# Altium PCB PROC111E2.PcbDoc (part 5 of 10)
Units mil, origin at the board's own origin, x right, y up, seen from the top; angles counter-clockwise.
Board outline 7700 x 2300 mil, 6 copper layers (Top Layer, GND 1, SIG 1, SIG 2, GND 2, Bottom Layer), stack 78.711 mil thick; 767 components, 596 nets, 2755 pads, 1578 vias.
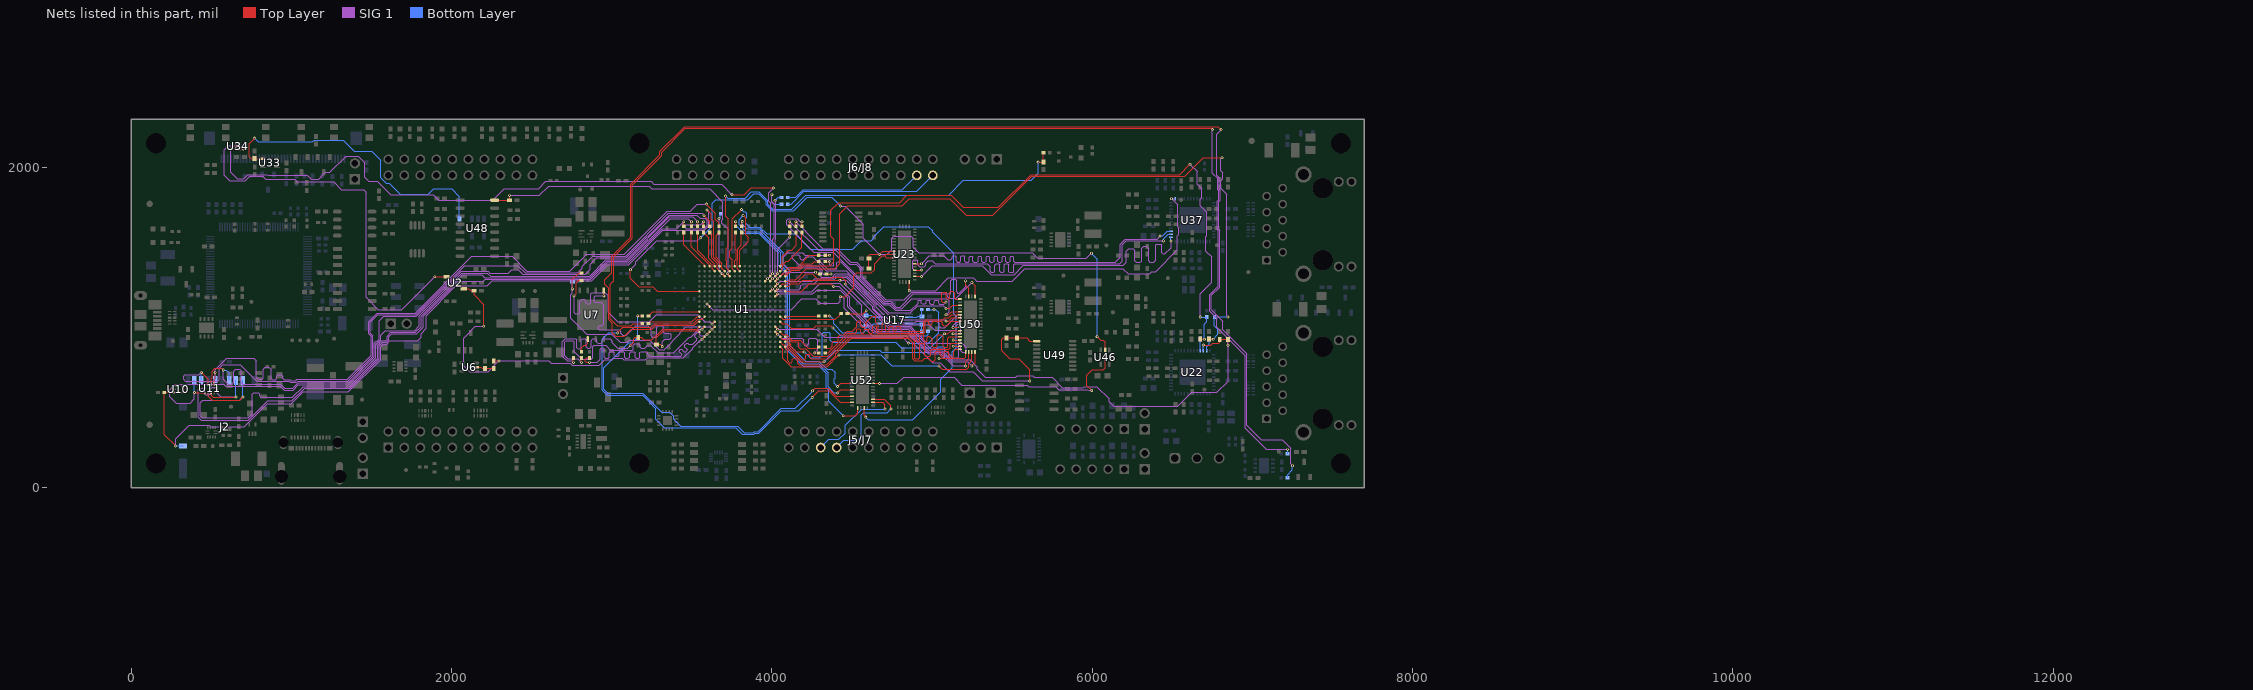
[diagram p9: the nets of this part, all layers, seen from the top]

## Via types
v1: diameter 18, hole 8, Top Layer to Bottom Layer, tented both sides, 1474 vias
v2: diameter 19.68, hole 7.87, Top Layer to Bottom Layer, tented both sides, 104 vias

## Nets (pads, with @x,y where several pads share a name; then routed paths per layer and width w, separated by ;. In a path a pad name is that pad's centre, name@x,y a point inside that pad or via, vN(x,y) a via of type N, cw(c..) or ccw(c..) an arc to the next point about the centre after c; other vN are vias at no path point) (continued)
AM263_ICSSM_MII0_TXD1: U23.27 U37.27 | length 2238.5
  Top Layer w5.3: U23.27@4892.17,1397.44 v1(4933.82,1397.44)
  SIG 1 w4.75: v1(4933.82,1397.44) 4982.58,1446.2 5073.64,1446.2 5097.17,1422.67 5116.6,1422.67 5125,1431.08 5125,1441.2 5130,1446.2 5145.03,1446.2 5150,1441.23 5150,1415.63 5157.93,1407.7 5171.95,1407.7 5180,1415.76 5180,1441.63 5184.57,1446.2 5200,1446.2 5204.29,1441.91 5204.29,1413.41 5210,1407.7 5225,1407.7 5231.71,1414.41 5231.71,1439.62 5237.09,1445 5250,1445 5255,1440 5255,1412.7 5260,1407.7 5280,1407.7 5286.71,1414.41 5286.71,1439.62 5292.09,1445 5305,1445 5310,1440 5310,1412.7 5315,1407.7 5330,1407.7 5336.71,1414.41 5336.71,1439.62 5342.09,1445 5355,1445 5360,1440 5360,1412.7 5365,1407.7 5380,1407.7 5386.71,1414.41 5386.71,1439.62 5392.09,1445 5405,1445 5410,1440 5410,1412.7 5415,1407.7 5430,1407.7 5436.71,1414.41 5436.71,1439.62 5442.09,1445 5455,1445 5460,1440 5460,1412.7 5465,1407.7 5480,1407.7 5486.71,1414.41 5486.71,1439.62 5492.09,1445 5505,1445 5510,1440 5510,1412.7 5515.18,1407.52 6145,1407.52 6175,1437.52 6175,1520.85 6206.45,1552.3 6404.57,1552.3 v1(6423.51,1571.24)
  Bottom Layer w5.3: v1(6423.51,1571.24) 6439.75,1571.24 6469.65,1601.14 U37.27@6491.32,1601.14
AM263_ICSSM_MII0_TXD2: U23.25 U37.26 | length 2245.1
  Top Layer w5.3: U23.25@4892.17,1358.07 v1(4933.82,1358.07)
  SIG 1 w4.75: v1(4933.82,1358.07) 4885,1358.07 4877.81,1365.27 4877.81,1413.87 4886.61,1422.67 4903.59,1422.67 4910,1416.26 4910,1391.44 4923.24,1378.19 4952.19,1378.19 4961,1387 4961,1401.85 4975.85,1416.69 4999.73,1416.69 5018.95,1397.47 5343.6,1397.47 5361.5,1379.57 5361.5,1351.08 5369.16,1343.42 5385.21,1343.42 5391.78,1349.99 5391.78,1389.25 5400,1397.47 5415,1397.47 5422.49,1389.98 5422.49,1350.49 5428.06,1344.92 5445.48,1344.92 5450,1349.43 5450,1390 5457.47,1397.47 5472.53,1397.47 5480,1390 5480,1348.38 5484.96,1343.42 5506.27,1343.42 5510,1347.15 5510,1392.47 5515,1397.47 6171.47,1397.47 6187.84,1413.84 6187.84,1517.25 6211.44,1540.85 v1(6444.47,1540.85)
  Bottom Layer w5.3: v1(6444.47,1540.85) 6444.47,1550.71 6475.21,1581.46 U37.26@6491.32,1581.46
AM263_ICSSM_MII0_TXD3: U23.23 U37.25 | length 2244.1
  Top Layer w5.3: U23.23@4892.17,1318.7 v1(4933.82,1318.7)
  SIG 1 w4.75: v1(4933.82,1318.7) 4999.46,1384.35 5314.02,1384.35 5369,1329.37 5512.23,1329.37 5570.29,1387.42 6195,1387.42 6213.36,1405.78 6213.36,1475.71 6227.65,1490 6254.55,1490 6265,1479.55 6265,1415.76 6275.11,1405.64 6300.52,1405.64 6307.97,1413.09 6307.97,1493.37 6320.6,1506 6336.86,1506 6351.36,1491.5 6351.36,1415.04 6360.4,1406 6383.17,1406 6397.17,1420 6397.17,1517.17 6401,1521 6430.92,1521 6434.76,1517.16 6434.76,1466.56 6442.03,1459.28 6452.69,1459.28 6492.17,1498.76 v1(6492.17,1540)
  Bottom Layer w5.3: U37.25@6491.32,1561.77 6491.32,1540.85 v1(6492.17,1540)
AM263_ICSSM_MII0_TXEN: U23.21 U37.37 | length 2239.7
  Top Layer w5.3: U23.21@4856.73,1283.27 4856.73,1230.38 v1(4857.11,1230)
  SIG 1 w4.75: v1(4857.11,1230) 5021.49,1230 5101.48,1309.99 5257.38,1309.99 5277.42,1289.95 5501.24,1289.95 5578.61,1367.32 6190.85,1367.32 6223.21,1334.96 6360.2,1334.96 6373.06,1347.82 6395.09,1347.82 6531.62,1484.35 6531.62,1572.37 6539.25,1580 6539.25,1622.97 6534.22,1628 6534.22,1764.68 v1(6495,1803.9)
  Bottom Layer w5.3: v1(6495,1803.9) U37.37@6516.91,1803.9
AM263_ICSSM_MII1_COL: R112.1 R124.2 R225.2 U1.C18 U22.45 | length 4456.8
  Top Layer w5.3: U1.C18@4082.57,1319.8 4086.6,1319.8 4122.5,1355.7 4170.68,1355.7 4201.68,1386.7 4363.56,1386.7 4387.19,1410.33 4387.19,1550.12 4367.66,1569.64 4367.66,1731.16 4416.75,1780.25 4796.75,1780.25 4840.66,1824.16 5119.95,1824.16 5194.97,1749.14 5412.42,1749.14 5618.28,1955 6545.79,1955 v1(6610,2019.21) ; R112.1@6674.39,926.46 v1(6700,926.46)
  SIG 1 w4.75: v1(6610,2019.21) 6655.14,1974.08 6655.14,1894.1 6684.3,1864.93 6684.3,1809.3 6674.82,1799.82 6674.82,1760.85 6716.13,1719.54 6716.13,1573.87 6710,1567.73 6710,1475.5 6745.5,1440 6745.5,1282.11 6674.39,1211 v1(6674.39,1065)
  Bottom Layer w5.3: U22.45@6674.39,853.9 6674.52,854.03 6674.52,926.32 R124.2@6674.39,926.46 v1(6700,926.46) 6700,1020 6715,1035 R225.2@6715,1064.94 6674.45,1064.94 v1(6674.39,1065)
AM263_ICSSM_MII1_RXCLK: U1.E16 U50.31 | length 1530.3
  Top Layer w5.3: v1(5131.16,1000.35) U50.31@5173.43,1000.35
  Top Layer w10: U1.E16@4019.57,1256.81 v1(4035.32,1272.56)
  SIG 1 w4: v1(4035.32,1272.56) 4051.82,1289.06 4114.06,1289.06
  SIG 1 w4.75: 4114.06,1289.06 4250.66,1289.06 4265.61,1304 4379.88,1304 4400.29,1324.4 4466.88,1324.4 4650,1141.28 4650,1127.38 4749.39,1027.99 4891.44,1027.99 4901.66,1038.21 5029.44,1038.21 5045,1022.66 5045,1007.89 5055.05,997.84 5080.12,997.84 5163.56,1081.29 5170.68,1081.29 5177.73,1074.24 5177.73,1041.58 5168.72,1032.57 5150.46,1032.57 5131.16,1013.27 v1(5131.16,1000.35)
AM263_ICSSM_MII1_RXD0: U1.F18 U50.42 | length 1527.9
  Top Layer w4: U1.F18@4082.57,1225.32 4113.77,1225.32 4114.06,1225.03
  Top Layer w5.3: 4114.06,1225.03 4115.16,1223.93 4182.78,1223.93 4232.43,1273.58 4368.23,1273.58 v1(4384.99,1256.82) ; v1(5248.23,759.55) 5267.91,779.23 U50.42@5267.91,846.81
  SIG 1 w4.75: v1(4384.99,1256.82) 4417.5,1256.82 4484.56,1189.75 4484.56,1133.75 4640.56,977.74 4847.67,977.74 4979.44,845.97 5058.54,845.97 5119.51,785 5222.77,785 v1(5248.23,759.55)
AM263_ICSSM_MII1_RXD1: U1.G16 U50.40 | length 1530
  Top Layer w5.3: v1(5208.86,759.55) 5208.86,785.31 5228.54,805 U50.40@5228.54,846.81
  Top Layer w10: U1.G16@4019.57,1193.82 v1(4035.32,1209.57)
  SIG 1 w4.75: v1(4035.32,1209.57) 4254.57,1209.57 4278.13,1233.13 4426.97,1233.13 4474.51,1185.59 4474.51,1129.58 4636.4,967.69 4843.5,967.69 4975.28,835.92 5054.38,835.92 5130.76,759.55 v1(5208.86,759.55)
AM263_ICSSM_MII1_RXD2: U1.E17 U50.37 | length 1526
  Top Layer w4: U1.E17@4051.07,1256.81 4066.82,1272.56 4101.95,1272.56 4113.62,1284.23 4114.06,1284.23
  Top Layer w5.3: 4114.06,1284.23 4158.05,1284.23 4210.42,1336.6 4250.64,1336.6 4281.86,1305.38 4367.8,1305.38 4377.05,1314.63 4436.95,1314.63 4460,1291.58 v1(4460,1271.09) ; v1(5131.77,882.24) U50.37@5173.43,882.24
  SIG 1 w4.75: v1(4460,1271.09) 4460,1264.54 4726.7,997.84 4860.42,997.84 4990.73,867.53 5070.26,867.53 5127.8,810 5158.56,810 5166.28,817.72 5166.28,868.95 5152.99,882.24 v1(5131.77,882.24)
AM263_ICSSM_MII1_RXD3: U1.E18 U50.35 | length 1529
  Top Layer w4: U1.E18@4082.57,1256.81 4104.96,1256.81
  Top Layer w5.3: 4104.96,1256.81 4121.72,1273.58 4171.45,1273.58 4192.65,1294.78 4372.19,1294.78 4372.51,1295.1 v1(4423.69,1295.1) ; v1(5131.77,921.61) U50.35@5173.43,921.61
  SIG 1 w4.75: v1(4423.69,1295.1) 4463.21,1295.1 4627.76,1130.55 4627.76,1113.02 4732.9,1007.89 4864.58,1007.89 4970.98,901.49 5157.7,901.49 5180,879.19 5180,853.61 5188.61,845 5208.86,845 5213.86,850 5213.86,875 5167.25,921.61 v1(5131.77,921.61)
AM263_ICSSM_MII1_RXDV: U1.F16 U50.33 | length 1526.7
  Top Layer w5.3: v1(5131.16,960.98) U50.33@5173.43,960.98
  Top Layer w10: U1.F16@4019.57,1225.32 v1(4035.32,1241.06)
  SIG 1 w4.75: v1(4035.32,1241.06) 4041.58,1234.81 4166.03,1234.81 4180,1248.78 4180,1259.38 4193.93,1273.3 4265,1273.3 4285.64,1293.95 4384.05,1293.95 4404.45,1314.35 4462.72,1314.35 4639.95,1137.12 4639.95,1115.05 4737.06,1017.94 4979.18,1017.94 5016.02,981.1 5142.47,981.1 5150.41,989.04 5150.41,1010.7 5159.71,1020 5173.32,1020 5177.73,1015.59 5177.73,969.09 5169.62,960.98 v1(5131.16,960.98)
AM263_ICSSM_MII1_RXER: R111.1 R123.2 R229.2 U1.F15 U22.46 | length 3862.9
  Top Layer w5.3: v1(6695,890) 6740,890 6751.09,901.09 6789.71,901.09 6795,906.38 6795,924.79 R111.1@6796.28,926.06 R123.2@6848,926.06 v1(6848,888.56)
  Top Layer w10: U1.F15@3988.08,1225.32 v1(4003.83,1241.06)
  SIG 1 w4.75: v1(4003.83,1241.06) 4019.95,1224.94 4048.81,1224.94 4051.93,1221.82 4248.36,1221.82 4302.6,1276.07 4415.5,1276.07 4415.71,1275.85 4422.39,1275.85 4560.42,1137.83 4560.42,1075.24 4647.86,987.79 4851.83,987.79 4983.6,856.02 5062.71,856.02 5120.89,797.83 5237.16,797.83 5283.33,751.67 5283.33,738.42 5332.03,689.72 5522.81,689.72 5531.21,698.12 5627.08,698.12 5636.35,688.86 5748.88,688.86 5813.88,623.85 5944.6,623.85 5951.6,630.85 6027.48,630.85 6104.93,553.4 6104.93,537.03 6133.73,508.23 6533.47,508.23 6619.77,594.53 6777.57,594.53 6848,664.96 v1(6848,888.56)
  Bottom Layer w5.3: U22.46@6694.07,853.9 6694.07,889.07 v1(6695,890) ; R229.2@6846.59,927.98 6846.59,889.97 v1(6848,888.56)
AM263_ICSSM_MII1_RXLINK: R110.1 R122.2 R227.2 U1.D18 U22.47 | length 4713.3
  Top Layer w5.3: U1.D18@4082.57,1288.31 4100.01,1288.31 4109.25,1297.55 4146.88,1297.55 4214.83,1365.5 4390.53,1365.5 4423.28,1398.25 4423.28,1708.76 4473.56,1759.05 4813.05,1759.05 4856.96,1802.96 5111.16,1802.96 5212.92,1701.21 5379.48,1701.21 5622.67,1944.4 6576.79,1944.4 6692.39,2060 v1(6810,2060) ; R110.1@6729.39,926.46 v1(6755,926.46)
  SIG 1 w4.75: v1(6810,2060) 6803.55,2053.55 6803.55,1979.56 6815.53,1967.58 6815.53,1930 6802.89,1917.36 6802.89,1868.09 6839.95,1831.03 6839.95,1072.44 v1(6846.59,1065.8)
  Bottom Layer w5.3: U22.47@6713.76,853.9 6713.76,879.37 6729.39,895 R122.2@6729.39,926.46 v1(6755,926.46) 6785,956.46 6785,987.75 6762.73,1010.01 R227.2@6762.73,1065.31 6846.11,1065.31 v1(6846.59,1065.8)
AM263_ICSSM_MII1_TXCLK: R86.1 U50.18 | length 1598.7
  Top Layer w5.3: R86.1@4111,1632.17 v1(4111,1660.23) ; v1(5248.23,1280.53) 5267.91,1260.84 U50.18@5267.91,1193.26
  SIG 1 w4.75: v1(4111,1660.23) 4290.62,1480.6 4399.37,1480.6 4484.34,1395.64 4525.74,1395.64 4555,1366.38 4555,1312.77 4705.46,1162.31 4741.59,1162.31 4777.03,1126.87 4800.47,1126.87 4883.5,1209.9 5081.16,1209.9 5107.69,1183.37 5151.08,1183.37 v1(5248.23,1280.53)
AM263_ICSSM_MII1_TXCLK_R: R86.2 U1.C16 | length 310.9
  Top Layer w5.3: v1(4111,1564.73) R86.2@4111,1592.8
  Top Layer w10: U1.C16@4019.57,1319.8 v1(4035.32,1335.55)
  SIG 1 w4: v1(4035.32,1335.55) 4035.32,1414.29
  SIG 1 w4.75: 4035.32,1414.29 4035.32,1489.06 v1(4111,1564.73)
AM263_ICSSM_MII1_TXD0: R81.1 U50.28 | length 1671.4
  Top Layer w5.3: R81.1@4331.94,1450.76 v1(4360,1450.76) ; v1(5086.77,1039.72) 5087.15,1040.1 5103.84,1040.1 5123.15,1059.41 U50.28@5173.43,1059.41
  SIG 1 w4.75: v1(4360,1450.76) 4205.76,1450.76 4190.82,1465.69 4097.29,1465.69 4071.14,1439.55 4071.14,1395.68 4092.58,1374.25 4280.76,1374.25 4300.52,1354.49 4300.52,1322.3 4308.78,1314.05 4375.72,1314.05 4396.13,1334.45 4471.04,1334.45 4728.5,1077 4779.38,1077 4807.3,1049.09 5077.41,1049.09 v1(5086.77,1039.72)
AM263_ICSSM_MII1_TXD0_R: R81.2 U1.B18 | length 251.2
  Top Layer w5.3: U1.B18@4082.57,1351.3 4108.55,1377.29 4159.8,1377.29 4233.26,1450.76 R81.2@4292.57,1450.76
AM263_ICSSM_MII1_TXD1: R82.1 U50.26 | length 1617.1
  Top Layer w5.3: R82.1@4187,1632.17 v1(4187,1660.23) ; v1(5086.77,1079.09) 5104.16,1079.09 5123.85,1098.78 U50.26@5173.43,1098.78
  SIG 1 w4.75: v1(4187,1660.23) 4176.22,1660.23 4156.97,1679.48 4102.64,1679.48 4091.48,1668.32 4091.48,1641.03 4262.23,1470.28 4383.28,1470.28 4701.77,1151.79 4737.89,1151.79 4772.86,1116.82 4810,1116.82 4873.1,1179.92 5092.29,1179.92 5106.3,1165.92 5106.3,1098.62 v1(5086.77,1079.09)
AM263_ICSSM_MII1_TXD1_R: R82.2 U1.B17 | length 304.3
  Top Layer w4: U1.B17@4051.07,1351.3 4068.69,1368.92 4068.69,1392.52 4076.15,1399.98
  Top Layer w5.3: 4076.15,1399.98 4090.36,1414.19 4101.39,1414.19 4187,1499.81 R82.2@4187,1592.8
AM263_ICSSM_MII1_TXD2: R83.1 U50.24 | length 1593.5
  Top Layer w5.3: R83.1@4339.69,1333.3 v1(4367.75,1333.3) ; v1(5086.77,1118.46) 5110.31,1118.46 5130,1138.15 U50.24@5173.43,1138.15
  SIG 1 w4.75: v1(4367.75,1333.3) 4320.82,1333.3 4313.29,1340.83 4313.29,1355.93 4284.87,1384.35 4173.89,1384.35 4126.25,1431.99 4126.25,1449.82 4131.71,1455.28 4162.45,1455.28 4175,1442.73 4175,1430.4 4183.34,1422.07 4193.93,1422.07 4212.49,1440.63 4254.37,1440.63 4340.2,1354.8 4464.91,1354.8 4729.02,1090.69 4864.78,1090.69 4909.09,1135 5070.23,1135 v1(5086.77,1118.46)
AM263_ICSSM_MII1_TXD2_R: R83.2 U1.D16 | length 309
  Top Layer w5.3: v1(4272.16,1344.87) 4283.66,1333.37 4300.24,1333.37 R83.2@4300.31,1333.3
  Top Layer w10: U1.D16@4019.57,1288.31 v1(4035.32,1304.06)
  SIG 1 w4.75: v1(4035.32,1304.06) 4076.13,1344.87 v1(4272.16,1344.87)
AM263_ICSSM_MII1_TXD3: R84.1 U50.22 | length 1639.7
  Top Layer w5.3: R84.1@4331.94,1410.76 v1(4360,1410.76) ; v1(5086.77,1157.83) 5065.63,1157.83 5060,1163.46 5060,1212.97 5066.68,1219.65 5083.67,1219.65 5086.77,1216.55 5086.77,1186.62 5094.7,1178.69 5102.75,1178.69 5108.69,1184.63 5108.69,1219.52 5115,1225.83 5129.17,1225.83 5140,1215 5140,1182.52 5145,1177.52 U50.22@5173.43,1177.52
  SIG 1 w4.75: v1(4360,1410.76) 4360,1390.84 4366.49,1384.35 4382.1,1384.35 4386.47,1388.71 4386.47,1405.96 ; 4386.49,1405.98 4386.49,1426.18 4382.66,1430 4301.19,1430 4293.86,1422.67 4293.86,1415.35 4344.21,1365 4402.22,1365 4405,1367.78 4405,1405.86 4409.89,1410.76 4428.59,1410.76 4697.6,1141.74 4733.73,1141.74 4768.7,1106.77 4866.65,1106.77 4912.39,1152.51 4912.39,1165.47 4916.79,1169.87 4928.94,1169.87 4932.42,1166.39 4932.42,1152.63 4938.17,1146.88 4956.11,1146.88 4963.82,1154.59 4963.82,1166.39 4967.3,1169.87 4982.03,1169.87 4985,1166.9 4985,1150.05 4990,1145.05 5010,1145.05 5014.57,1149.62 5014.57,1163.89 5020,1169.32 5034.12,1169.32 5040,1163.44 5040,1150.05 5045,1145.05 5073.99,1145.05 v1(5086.77,1157.83)
AM263_ICSSM_MII1_TXD3_R: R84.2 U1.C17 | length 279.2
  Top Layer w5.3: U1.C17@4051.07,1319.8 4068.04,1336.78 4088.58,1336.78 4118.11,1366.3 4166.29,1366.3 4197.29,1397.3 4251.73,1397.3 4265.18,1410.76 R84.2@4292.57,1410.76
AM263_ICSSM_MII1_TXEN: R85.1 U50.20 | length 1660.3
  Top Layer w5.3: R85.1@4149,1632.17 v1(4149,1660.23) ; v1(5208.86,1290.74) 5208.86,1264.69 5228.54,1245 U50.20@5228.54,1193.26
  SIG 1 w4.75: v1(4149,1660.23) 4209.95,1599.28 4209.95,1598.74 4318.04,1490.65 4407.8,1490.65 4492.77,1405.69 4529.9,1405.69 4565.05,1370.54 4565.05,1316.93 4709.62,1172.36 4826.69,1172.36 4874.28,1219.95 5085.33,1219.95 5095.23,1210.05 5111.68,1210.05 5116.23,1214.6 5116.23,1291.23 5124.45,1299.45 5145.55,1299.45 5154.88,1290.12 5154.88,1221.62 5161.5,1215 5168.49,1215 5208.86,1255.37 v1(5208.86,1290.74)
AM263_ICSSM_MII1_TXEN_R: R85.2 U1.A17 | length 263.9
  Top Layer w5.3: U1.A17@4051.07,1382.8 4051.07,1387.13 4065.55,1401.61 4065.55,1443.56 4105.13,1483.15 4122.33,1483.15 4152.94,1513.76 4152.94,1588.85 R85.2@4149,1592.8
AM263_IEP0_EDC_SYNC_OUT0: J6/J8.72 R88.1 | length 862.6
  Bottom Layer w5.3: R88.1@4098.66,1812.24 4147.24,1812.24 4195.51,1860.51 4814.68,1860.51 J6/J8.72@4904.17,1950
AM263_IEP0_EDC_SYNC_OUT0_R: R88.2 U1.D15 | length 569.2
  Top Layer w10: U1.D15@3988.08,1288.31 v1(4003.83,1304.06)
  SIG 1 w4: v1(4003.83,1304.06) 4020.32,1320.55 4020.32,1414.29
  SIG 1 w4.75: v1(4018.83,1791.62) 4023.81,1786.64 4023.81,1555.11 4020.32,1551.62 4020.32,1414.29
  Bottom Layer w5.3: v1(4018.83,1791.62) 4039.45,1812.24 R88.2@4059.29,1812.24
AM263_IEP0_EDIO_DATA_IN_OUT31: J6/J8.71 R87.1 | length 980.4
  Bottom Layer w5.3: R87.1@4098.66,1769.24 4119.24,1769.24 4199.52,1849.52 4903.7,1849.52 J6/J8.71@5004.17,1950
AM263_IEP0_EDIO_DATA_IN_OUT31_R: R87.2 U1.C15 | length 636.2
  Top Layer w10: U1.C15@3988.08,1319.8 v1(4003.83,1335.55)
  SIG 1 w4: v1(4003.83,1335.55) 4003.83,1414.29
  SIG 1 w4.75: v1(3999.3,1828.52) 3999.58,1828.25 3999.58,1783.65 4013.76,1769.47 4013.76,1559.27 4003.83,1549.33 4003.83,1414.29
  Bottom Layer w5.3: v1(3999.3,1828.52) 3999.3,1783.54 4013.6,1769.24 R87.2@4059.29,1769.24
AM263_INT1_PB_GPIO123: U1.D14 U34.4 | length 4549.2
  Top Layer w4: v1(621.55,2115.47) U34.4@651.22,2115.47
  Top Layer w5.3: v1(3750,1830) 3827.92,1830 3869.54,1871.62 4009.75,1871.62 v1(4010,1871.38)
  Top Layer w10: U1.D14@3956.58,1288.31 v1(3972.33,1304.06)
  SIG 1 w4: v1(3972.33,1304.06) 3988.83,1320.55 3988.83,1414.29
  SIG 1 w4.75: v1(621.55,2115.47) 620.75,2114.67 620.75,1967.65 660.41,1928 699.92,1928 726.78,1954.85 848.11,1954.85 852.86,1950.1 1098.52,1950.1 1122.87,1925.75 1168.51,1925.75 1210.41,1967.65 1237.15,1967.65 1340,2070.5 1415,2070.5 1457,2028.5 1457,1939.5 1483,1913.5 1535.02,1913.5 1620,1828.52 1884.51,1828.52 1918.04,1795 2256.51,1795 2328.43,1866.92 2542.73,1866.92 2587.88,1912.07 3244.73,1912.07 3261.64,1895.15 3684.85,1895.15 v1(3750,1830) ; 3988.83,1414.29 3988.83,1547.33 3993.66,1552.16 3993.66,1775.35 3980.05,1788.96 3980.05,1841.43 v1(4010,1871.38)
AM263_LED_ENABLE_GPIO25: R278.2 U1.C7 U48.8 | length 2011.2
  Top Layer w5.3: U48.8@2267.28,1795 R278.2@2361.38,1795 v1(2361.38,1825)
  Top Layer w10: v1(3720.36,1335.55) U1.C7@3736.11,1319.8
  SIG 1 w4: v1(3720.36,1335.55) 3720.36,1336.08 3725.31,1341.03 3725.31,1429.98
  SIG 1 w4.75: v1(2361.38,1825) 2547.62,1825 2604.54,1881.92 3232.22,1881.92 3249.14,1865 3612.11,1865 3693.94,1783.18 3693.94,1674.39 3687.75,1668.2 3687.75,1652.26 3725.31,1614.7 3725.31,1429.98
AM263_LED_GPIO26: R303.1 R304.2 U1.B7 | length 2775.8
  Top Layer w4: 3718.25,1414.29 3718.49,1414.06 3718.49,1368.92 U1.B7@3736.11,1351.3
  Top Layer w5.3: v1(3710,1820) 3710,1695.65 3727.37,1678.28 3727.37,1502.62 3715.65,1490.9 3715.65,1416.89 3718.25,1414.29 ; v1(5662,2032.26) R304.2@5695.31,2032.26 R303.1@5695.31,2090.86
  Bottom Layer w5.3: v1(3710,1820) 3710.6,1820 3722.29,1808.32 3832.65,1808.32 3871.7,1847.37 3918.43,1847.37 3974.4,1791.4 3974.4,1768.74 4004.86,1738.28 4123.33,1738.28 4210.05,1825 5102.5,1825 5195.5,1918 5618.43,1918 5662,1961.58 v1(5662,2032.26)
AM263_LIN1_RXD: U1.A9 U52.33 | length 1944.5
  Top Layer w4: 3797.83,1414.29 3797.83,1384.07 U1.A9@3799.1,1382.8
  Top Layer w5.3: 3797.83,1414.29 3797.83,1483.15 3851.19,1536.5 3851.19,1562.07 3835,1578.26 3835,1684.41 v1(3820,1699.41) ; v1(4408.39,591.26) 4428.07,610.95 U52.33@4500.04,610.94
  Bottom Layer w5.3: v1(3820,1699.41) 3794,1673.41 3794,1642.5 3837.33,1599.17 3920.87,1599.17 4055,1465.05 4055,1388.67 4098.83,1344.83 4098.83,870.99 4195,774.82 4293.44,774.82 4350.12,718.14 4350.12,628.17 4387.04,591.26 v1(4408.39,591.26)
AM263_LIN1_TXD: R297.1 U52.31 | length 1522.4
  Top Layer w5.3: R297.1@3811,1632.61 3811,1654.23 3814,1657.23 v1(3814,1660.67) ; v1(4408.39,630.63) 4428.07,650.32 U52.31@4500.04,650.32
  Bottom Layer w5.3: v1(3814,1660.67) 3814,1643 3841.88,1615.12 3919.92,1615.12 4070,1465.04 4070,1395 4110.29,1354.71 4110.29,889.4 4209.85,789.85 4293.41,789.85 4344.13,739.13 4373.61,739.13 4394.05,718.69 4394.05,683.88 4388.25,678.09 4388.25,650.19 4407.81,630.63 v1(4408.39,630.63)
AM263_LIN1_TXD_R: R297.2 U1.B9 | length 259.9
  Top Layer w4: 3783.35,1414.29 3783.35,1367.05 U1.B9@3799.1,1351.3
  Top Layer w5.3: 3783.35,1414.29 3783.35,1418.8 3786.5,1421.94 3786.5,1492.41 3809.52,1515.44 3809.52,1591.76 R297.2@3811,1593.24
AM263_LIN2_RXD: U1.B8 U52.41 | length 3558.7
  Top Layer w4: 3751.86,1380 3751.86,1367.05 U1.B8@3767.61,1351.3
  Top Layer w5.3: 3751.86,1380 3751.86,1422.06 3736.85,1437.07 3736.85,1478.36 3752.63,1494.14 3752.63,1678.98 v1(3810,1736.34) ; U52.41@4574.84,496.77 4574.84,451.2 4585.49,440.55 v1(4585.49,440)
  Bottom Layer w5.3: v1(3810,1736.34) 3823.34,1723 3832,1723 3842.5,1712.5 3842.5,1687 3836,1680.5 3836,1649.5 3858.59,1626.91 3923.12,1626.91 3965.77,1584.26 4145,1584.26 4239.53,1489.72 4502.96,1489.72 4555.91,1542.67 4619.9,1542.67 4633.91,1556.68 4633.91,1565.54 4698.62,1630.25 4975.47,1630.25 5003.34,1602.38 5003.34,1593.17 5134.52,1461.99 5134.52,1085.62 5151.3,1068.85 5151.3,874.15 5125,847.86 5125,747.97 5052.64,675.61 5052.64,652.24 5053.48,651.41 5053.48,599.64 4877.46,423.62 4601.87,423.62 v1(4585.49,440)
AM263_LIN2_RXD_PR0_PRU0_GPIO11: J5/J7.43 U52.2 | length 638.1
  Top Layer w5.3: U52.2@4629.96,532.2 4691.22,532.2 4705,518.43 4705,490.59 v1(4705.59,490)
  Bottom Layer w5.3: J5/J7.43@4304.17,250 4355,300.83 4418.22,300.83 4457.78,340.39 4457.78,387.87 4559.9,490 v1(4705.59,490)
AM263_LIN2_TXD: R166.1 U52.39 | length 1760.3
  Top Layer w5.3: R166.1@3773,1632.17 v1(3773,1660.23) ; v1(4444.77,448.84) 4445.11,448.5 4519.71,448.5 4535.47,464.27 U52.39@4535.47,496.77
  Bottom Layer w5.3: v1(3773,1660.23) 3773,1638 3822.43,1588.57 3916.48,1588.57 4040,1465.06 4040,1388.66 4089.53,1339.13 4089.53,865.3 4195.86,758.98 4294.3,758.98 4339.52,713.75 4339.52,623.78 4354.64,608.66 4354.64,538.97 v1(4444.77,448.84)
AM263_LIN2_TXD_PR0_PRU0_GPIO9: J5/J7.44 U52.3 | length 666.9
  Top Layer w5.3: U52.3@4629.96,551.89 4700.67,551.89 4742.56,510 v1(4742.56,490.87)
  Bottom Layer w5.3: J5/J7.44@4404.17,250 4449.17,295 4535.31,295 4558.86,318.54 4558.86,454.51 4572.72,468.37 4720.06,468.37 v1(4742.56,490.87)
AM263_LIN2_TXD_R: R166.2 U1.A8 | length 216.7
  Top Layer w4: U1.A8@3767.61,1382.8 3767.61,1414.29
  Top Layer w5.3: 3767.61,1414.29 3767.61,1418.04 3775.9,1426.33 3775.9,1481.99 3770.48,1487.41 3770.48,1590.27 R166.2@3773,1592.8
AM263_MCAN0_RX: R249.1 U1.M1 | length 7982.7
  Top Layer w5.3: U1.M1@3547.13,1036.34 3537.57,1036.34 3515.01,1013.78 3272.76,1013.78 3248.41,989.43 3121.84,989.43 3078.22,945.81 3025.74,945.81 3003.38,968.17 3003.38,1025.67 2979.75,1049.3 2979.75,1246.34 2956.08,1270.01 2956.08,1298.09 3000,1342 3000,1445.92 3116.47,1562.39 3116.47,1893.41 3300,2076.94 3300,2099.44 3455.44,2254.89 6785.11,2254.89 v1(6805,2235)
  SIG 1 w4.75: v1(6805,2235) 6777.03,2207.03 6777.03,1951.63 6792.84,1935.82 6792.84,1863.93 6800.05,1856.72 6800.05,1793.84 6790.75,1784.54 6790.75,1612.85 6795.75,1607.85 6795.75,1252.32 6743.49,1200.06 6743.49,1110.67 6815.53,1038.63 6815.53,984.47 6964.3,835.7 6964.3,390.66 7054.96,300 7185.73,300 7238.93,246.79 7238.93,147.52 v1(7250,136.46)
  Bottom Layer w5.3: R249.1@7219.69,61.46 7219.69,79.68 7250,110 v1(7250,136.46)
AM263_MCAN0_TX: R167.1 R245.1 | length 7248.8
  Top Layer w5.3: R167.1@3190,1024.38 3134.37,1024.38 3121.57,1011.58 3032.47,1011.58 2990.35,1053.69 2990.35,1269.87 3010.6,1290.12 3010.6,1441.52 3127.1,1558.02 3127.1,1889.05 3310.6,2072.55 3310.6,2095.05 3459.83,2244.29 6740.71,2244.29 v1(6750,2235)
  SIG 1 w4.75: v1(6750,2235) 6750,1964.45 6782.79,1931.66 6782.79,1859.76 6790,1852.55 6790,1798 6780.7,1788.7 6780.7,1608.69 6785.7,1603.69 6785.7,1256.49 6733.44,1204.22 6733.44,1101.56 6777.03,1057.97 6777.03,1001.63 6954.25,824.41 6954.25,370.75 7086.18,238.82 v1(7219.69,238.82)
  Bottom Layer w5.3: R245.1@7219.69,211.46 v1(7219.69,238.82)
AM263_MCAN0_TX_R: R167.2 U1.L1 | length 335.8
  Top Layer w5.3: R167.2@3229.37,1024.38 3239.99,1035 3500,1035 3532.83,1067.83 U1.L1@3547.13,1067.83
AM263_MCAN1_RX: U1.L2 U52.37 | length 2870.9
  Top Layer w4: 3545,1052.09 3562.88,1052.09 U1.L2@3578.63,1067.83
  Top Layer w5.3: v1(3034.25,965.34) 3068.94,1000.03 3242.98,1000.03 3267.33,1024.38 3509.45,1024.38 3537.16,1052.09 3545,1052.09 ; v1(4251.73,562.53) 4292.39,603.19 4353.85,603.19 4424.84,532.2 U52.37@4500.04,532.2
  Bottom Layer w5.3: v1(3034.25,965.34) 2980,965.34 2939.88,925.21 2939.88,606.54 2969.86,576.56 3191.82,576.56 3275,493.37 3275,425.55 3327.05,373.5 3772.78,373.5 3813.13,333.15 3887.64,333.15 3892.69,338.2 3916.73,338.2 4058.4,479.86 4168.53,479.86 4251.19,562.53 v1(4251.73,562.53)
AM263_MCAN1_TX: R168.1 U52.35 | length 2396.4
  Top Layer w5.3: v1(3161.94,1072.38) R168.1@3190,1072.38 ; v1(4253.02,605) 4269.57,621.55 4350.48,621.55 4400.46,571.57 U52.35@4500.04,571.57
  Bottom Layer w5.3: v1(3161.94,1072.38) 3161.94,940.14 3126.83,905.04 3106.91,905.04 2950.48,748.6 2950.48,613.16 2973.72,589.92 3193.45,589.92 3311.99,471.38 3361.58,471.38 3387.12,445.84 3387.12,426.65 3429.27,384.5 3786.22,384.5 3815.48,355.24 3815.48,355.19 3826.91,343.75 3883.25,343.75 3889.5,350 3913.54,350 4059.29,495.75 4146.65,495.75 4253.02,602.12 v1(4253.02,605)
AM263_MCAN1_TX_R: R168.2 U1.K1 | length 328.9
  Top Layer w4: 3515.64,1099.33 U1.K1@3547.13,1099.33
  Top Layer w5.3: R168.2@3229.37,1072.38 3256.32,1099.33 3515.64,1099.33
AM263_MDIO0_MDC: R61.1 R63.1 U17.9 | length 125.7
  Bottom Layer w5.3: U17.9@4855.28,1024.06 4930.59,1024.06 R63.1@4935.59,1019.06 R61.1@4935.59,975.79
AM263_MDIO0_MDC_R: R61.2 U1.M17 | length 995.7
  Top Layer w4: U1.M17@4051.07,1036.34 4065.59,1021.81
  Top Layer w5.3: 4065.59,1021.81 4093.38,1021.81 4121.5,993.69 4259.91,993.69 4276.4,1010.18 4366.95,1010.18 v1(4380,997.13)
  Bottom Layer w5.3: v1(4380,997.13) 4428.34,948.79 4966.19,948.79 4975,957.6 4975,975.75 R61.2@4974.96,975.79
AM263_MDIO0_MDIO: R62.1 R64.1 U17.7 | length 125.7
  Bottom Layer w5.3: U17.7@4855.28,1063.43 4904.79,1063.43 4909.79,1068.43 R64.1@4935.59,1068.43 R62.1@4935.59,1111.7
AM263_MDIO0_MDIO_R: R62.2 U1.N16 | length 1289.2
  Top Layer w10: U1.N16@4019.57,1004.84 v1(4035.32,989.09)
  SIG 1 w4: v1(4035.32,989.09) 4114.06,989.09
  SIG 1 w4.75: 4114.06,989.09 4278.7,989.09 4330.25,937.54 4815.65,937.54 4851.26,901.93 v1(4853.62,901.93)
  Bottom Layer w5.3: v1(4853.62,901.93) 4974.46,901.93 5040,967.46 5040,1094.07 5022.46,1111.61 v1(5011.92,1111.61) 5011.82,1111.7 R62.2@4974.96,1111.7
AM263_MMC0_CD: J2.9 R40.1 U1.A5 U10.3 | length 4997.5
  Top Layer w5.3: U10.3@263.65,594.53 R40.1@204.68,594.53 204.68,330.57 v1(275.17,260.08) ; v1(3594.38,1733.21) 3622,1705.59 3622,1675.5 3635,1662.5 3635,1439.81 3673.12,1401.69 U1.A5@3673.12,1382.8
  SIG 1 w4.75: v1(275.17,260.08) 275.17,305 360.08,389.91 486.18,389.91 495.34,380.75 703.53,380.75 847.11,524.33 999.19,524.33 1072.75,597.89 1355.24,597.89 1556.94,799.59 1556.94,880.99 1572.11,896.16 1593.69,896.16 1613.79,916.26 1786.5,916.26 1808.14,937.9 1808.14,961.84 1840,993.7 1840,1073.63 2026.56,1260.2 2222.97,1260.2 2253.28,1290.51 2873.12,1290.51 2975.46,1392.85 3105.2,1392.85 3318.05,1605.7 3576.54,1605.7 3605.2,1634.37 3605.2,1722.39 v1(3594.38,1733.21)
  Bottom Layer w5.3: v1(275.17,260.08) 275.25,260.16 J2.9@321.97,260.16
AM263_MMC0_CLK: J2.5 R33.2 U11.1 | length 4372.9
  Top Layer w5.3: U11.1@517.72,646.57 517.72,676.24 522.76,681.27 v1(522.76,719.45) ; v1(3590,1770) 3645.4,1714.6 3645.4,1676.1 3669,1652.5 R33.2@3669,1632.17
  SIG 1 w4.75: v1(522.76,719.45) 524.7,721.39 524.7,735.57 595.21,806.09 764.45,806.09 780,790.54 780,689.1 791.64,677.46 815.94,677.46 823.99,685.51 823.99,739.81 835.39,751.21 858.79,751.21 871.44,738.56 871.44,680.97 878.15,674.26 900,674.26 907.66,681.93 907.66,698.12 915,705.46 935.75,705.46 945,696.21 945,684.26 955,674.26 991.71,674.26 998.75,667.23 1025.84,667.23 1033.66,675.05 1346.34,675.05 1496.64,825.35 1496.64,943.48 1480.7,959.42 1480.7,1037.14 1533.73,1090.16 1771.25,1090.16 2124.63,1443.54 2376.7,1443.54 2469.43,1350.81 2737.39,1350.81 2844.29,1457.71 3077.71,1457.71 3344.99,1724.99 3488.2,1724.99 3533.21,1770 v1(3590,1770)
  Bottom Layer w5.3: J2.5@522.76,669.61 v1(522.76,719.45)
AM263_MMC0_CLK_R: R33.1 U1.B6 | length 271.2
  Top Layer w4: 3687.64,1387.89 3687.64,1368.27 U1.B6@3704.61,1351.3
  Top Layer w5.3: R33.1@3669,1592.8 3650.97,1574.76 3650.97,1438.83 3687.64,1402.16 3687.64,1387.89
AM263_MMC0_CMD: J2.3 R34.2 U11.2 | length 4495.2
  Top Layer w5.3: U11.2@498.04,646.57 498.04,678.5 503.23,683.69 503.23,727.54 519.46,743.77 563.58,743.77 v1(573.09,734.25) ; R34.2@3573,1632.17 v1(3573,1660.23)
  SIG 1 w4.75: v1(573.09,734.25) 573.09,677.22 605.31,645 628.72,645 640,656.28 640,727.32 652.68,740 676.6,740 685,731.6 685,655 695,645 930.89,645 957.03,618.86 1005.9,618.86 1041.99,654.95 1355.45,654.95 1516.74,816.24 1516.74,897.64 1546.64,927.54 1546.64,1040.36 1576.34,1070.06 1779.58,1070.06 2059.52,1350 2227.48,1350 2238.4,1339.08 2353.92,1339.08 2373.99,1359.16 2413.92,1359.16 2442.37,1330.71 2832.56,1330.71 2864.93,1363.08 2864.93,1393.43 2906.08,1434.58 3090.08,1434.58 3357.45,1701.95 3531.28,1701.95 3552.48,1680.75 3584.54,1680.75 3595.15,1670.14 3595.15,1638.53 3572.37,1615.75 3465,1615.75 3458.15,1622.6 3458.15,1634.13 3465,1640.98 3553.75,1640.98 v1(3573,1660.23)
  Bottom Layer w5.3: v1(573.09,734.25) 592.45,734.25 609.37,717.33 J2.3@609.37,669.61
AM263_MMC0_CMD_R: R34.1 U1.A4 | length 238.4
  Top Layer w5.3: R34.1@3573,1592.8 3605,1560.8 3605,1433.11 3639.62,1398.48 3639.62,1384.79 U1.A4@3641.62,1382.8
AM263_MMC0_D0: J2.7 R35.2 U11.3 | length 4380
  Top Layer w5.3: v1(436.14,719.45) 478.35,677.24 U11.3@478.35,646.57 ; v1(3575,1700) 3611,1664 R35.2@3611,1632.17
  SIG 1 w4.75: v1(436.14,719.45) 420.83,704.14 334.14,704.14 325,695 325,675 335,665 539.81,665 549.08,674.26 549.08,745.74 569.32,765.98 680,765.98 781.77,664.21 984.38,664.21 991.41,657.18 1030,657.18 1037.82,665 1351.29,665 1506.69,820.4 1506.69,947.65 1490.75,963.58 1490.75,1032.97 1537.89,1080.11 1775.42,1080.11 2080.3,1385 2413.37,1385 2457.61,1340.76 2786.32,1340.76 2814.93,1369.37 2814.93,1381.73 2879.17,1445.98 3087.27,1445.98 3353.29,1712 3563,1712 v1(3575,1700)
  Bottom Layer w5.3: J2.7@436.14,669.61 v1(436.14,719.45)
AM263_MMC0_D0_R: R35.1 U1.B5 | length 267.2
  Top Layer w4: 3657.37,1390.67 3657.37,1367.05 U1.B5@3673.12,1351.3
  Top Layer w5.3: R35.1@3611,1592.8 3624.4,1579.4 3624.4,1435.42 3657.37,1402.45 3657.37,1390.67
AM263_MMC0_D1: J2.8 R36.2 U11.6 | length 4334
  Top Layer w5.3: v1(393.42,593.25) 393.59,593.43 U11.6@458.67,593.43 ; R36.2@3535,1632.17 v1(3535,1660.23)
  SIG 1 w4.75: v1(393.42,593.25) 393.42,554.93 366.39,527.91 278.68,527.91 240,566.59 240,610 274.25,644.25 576.46,644.25 587.24,633.46 928.21,633.46 952.86,608.81 1010.06,608.81 1042.09,640.84 1355.56,640.84 1526.79,812.07 1526.79,893.48 1556.69,923.38 1556.69,951.15 1585.54,980 1768.09,980 1798.09,1010 1798.09,1074.36 2063.68,1339.95 2223.32,1339.95 2242.61,1320.66 2860.63,1320.66 2962.97,1423 3092.71,1423 3359.71,1690 3505.23,1690 v1(3535,1660.23)
  Bottom Layer w5.3: J2.8@392.83,669.61 392.83,593.83 v1(393.42,593.25)
AM263_MMC0_D1_R: R36.1 U1.B4 | length 285.7
  Top Layer w4: 3617.28,1398.59 3625.87,1390 3625.87,1367.05 U1.B4@3641.62,1351.3
  Top Layer w5.3: R36.1@3535,1592.8 3535.16,1592.64 3535.16,1480.71 3617.28,1398.59
AM263_MMC0_D2: J2.1 R37.2 U11.7 | length 4565.1
  Top Layer w5.3: U11.7@478.35,593.43 478.35,571.65 505.48,544.52 674.75,544.52 v1(695.98,565.76) ; R37.2@3497,1632.17 v1(3497,1660.23)
  SIG 1 w4.75: v1(695.98,565.76) 676.74,546.51 446.51,546.51 430.11,530.11 430.11,447.99 441.64,436.46 730.81,436.46 755,460.65 755,583.25 765,593.25 791.75,593.25 800,585 800,572.73 808.85,563.88 1004.88,563.88 1071.8,630.8 1359.72,630.8 1536.84,807.91 1536.84,889.31 1563.79,916.26 1585.36,916.26 1596.64,927.54 1596.64,946.2 1620.39,969.95 1773.09,969.95 1808.14,1005 1808.14,1070.2 2067.84,1329.9 2188.43,1329.9 2207.72,1310.61 2864.79,1310.61 2967.14,1412.95 3096.88,1412.95 3363.88,1679.95 3477.28,1679.95 v1(3497,1660.23)
  Bottom Layer w5.3: v1(695.98,565.76) J2.1@695.98,669.61
AM263_MMC0_D2_R: R37.1 U1.A3 | length 257.6
  Top Layer w4: 3584.29,1415.65 3610.12,1389.82 U1.A3@3610.12,1382.8
  Top Layer w5.3: R37.1@3497,1592.8 3496.11,1591.91 3496.11,1503.83 3584.29,1415.65
AM263_MMC0_D3: J2.2 R38.2 U11.8 | length 4475.8
  Top Layer w5.3: U11.8@498.04,593.43 498.04,577.3 509.79,565.55 652.47,565.55 v1(652.68,565.76) ; R38.2@3449,1632.17 v1(3449,1660.23)
  SIG 1 w4.75: v1(652.68,565.76) 558.64,565.76 535,589.4 535,614.59 524.59,625 504.26,625 495.34,616.08 495.34,589.74 485,579.4 463.85,579.4 455,588.25 455,608.19 444.33,618.86 423.61,618.86 415.82,611.07 415.82,439.18 435,420 728.57,420 850.08,541.51 1002.16,541.51 1081.39,620.74 1363.88,620.74 1546.89,803.75 1546.89,885.15 1567.95,906.21 1589.53,906.21 1606.69,923.38 1606.69,942.03 1624.56,959.9 1782.24,959.9 1822.76,1000.41 1822.76,1070.6 2041.04,1288.88 2197.21,1288.88 2208.89,1300.56 2868.96,1300.56 2971.3,1402.9 3101.04,1402.9 3313.89,1615.75 3404.52,1615.75 v1(3449,1660.23)
  Bottom Layer w5.3: v1(652.68,565.76) J2.2@652.68,669.61
AM263_MMC0_D3_R: R38.1 U1.A2 | length 263.9
  Top Layer w4: 3552.08,1414.29 3578.63,1387.74 U1.A2@3578.63,1382.8
  Top Layer w5.3: R38.1@3449,1592.8 3449,1517.05 3551.76,1414.29 3552.08,1414.29
AM263_MMC0_WP: R41.1 U1.C6 | length 408.5
  Top Layer w10: v1(3688.87,1335.55) U1.C6@3704.61,1319.8
  SIG 1 w4: 3669.62,1414.29 3669.62,1354.8 v1(3688.87,1335.55)
  SIG 1 w4.75: 3669.62,1414.29 v1(3669.62,1679.88)
  Bottom Layer w5.3: v1(3669.62,1679.88) 3678.01,1688.27 R41.1@3678.01,1710.32
AM263_MUX_EN_GPIO58: R288.2 R290.2 U1.F1 U23.8 U46.2 U52.8 | length 6834
  Top Layer w4: 3515.64,1225.32 U1.F1@3547.13,1225.32
  Top Layer w5.3: v1(3115.7,1360.5) 3115.7,1306.45 3168.26,1253.89 3254.61,1253.89 3283.18,1225.32 3515.64,1225.32 ; R290.2@4605.35,1367.93 R288.2@4605.35,1430.9 4605.35,1449.54 4612.31,1456.5 v1(4670.59,1456.5) 4690.28,1476.18 U23.8@4762.24,1476.18 ; U52.8@4629.96,650.32 v1(4671.61,650.32) ; v1(5996.69,607.19) 5966.5,637.37 5966.5,701.5 6001.5,736.5 6067.5,736.5 6080,749 U46.2@6080,859.29 6080,908.65 6068.88,919.76 6052.77,919.76 v1(6030.69,941.85)
  SIG 1 w4.75: v1(3115.7,1360.5) 3149.5,1394.3 3149.5,1408.72 3281.28,1540.5 3534.57,1540.5 v1(3554.94,1560.88) ; v1(4428.41,1758) 4456.08,1758 4568.5,1645.58 4568.5,1558.59 v1(4670.59,1456.5) 4719.41,1456.5 4748.03,1485.12 4748.03,1556.28 4760.91,1569.15 4869.07,1569.15 4883.22,1555 4883.22,1500.17 4917.09,1466.3 5625,1466.3 5659.44,1431.86 5963.55,1431.86 v1(5994.69,1463) ; v1(4671.61,650.32) 4782.02,650.32 4821.54,689.84 5136.86,689.84 5186.19,640.5 5593.11,640.5 5602.86,630.75 5772.36,630.75 5792.11,611 5973,611 5976.81,607.19 v1(5996.69,607.19)
  Bottom Layer w5.3: v1(3554.94,1560.88) 3625.87,1631.81 3625.87,1775.87 3647.72,1797.72 3850.05,1797.72 3886.85,1834.52 3916.29,1834.52 3962.64,1788.18 3962.64,1765.51 4000.47,1727.68 4134.55,1727.68 4219.11,1812.24 4374.16,1812.24 v1(4428.41,1758) ; v1(5994.69,1463) 6030.69,1427 v1(6030.69,941.85)
AM263_PORZ: R6.2 R19.1 U1.R2 U2.4 | length 2319.5
  Top Layer w5.3: U2.4@2075.37,1242.05 2104.75,1242.05 2117.66,1229.13 R6.2@2139.09,1229.13 2139.09,1203.83 2199.68,1143.24 v1(2199.68,1007.17) ; R19.1@2262.84,791.01 2294.9,791.01 v1(2295,790.91)
  Top Layer w10: v1(3562.88,926.1) U1.R2@3578.63,941.85
  SIG 1 w4.75: v1(2199.68,1007.17) 2148.21,1007.17 2075,933.96 2075,761.73 2113.34,723.39 2227.48,723.39 v1(2295,790.91) 2605,790.91 2620.94,774.97 2739.96,774.97 2752.03,762.9 2921.96,762.9 2955.87,796.81 3001.93,796.81 3011.54,806.41 3065.4,806.41 3075,796.81 3209.85,796.81 3223.9,810.85 3447.22,810.85 3503.75,867.38 3503.75,872.19 3551.59,920.03 3556.81,920.03 v1(3562.88,926.1)
AM263_PORZ_PB: U2.1 U34.6 | length 2549
  Top Layer w4: U34.6@678.78,2115.47 v1(700,2115.47)
  Top Layer w5.3: v1(1893.92,1316.68) 1966.94,1316.68 U2.1@1967.11,1316.85
  SIG 1 w5.3: v1(700,2115.47) 680.48,2135 605,2135 579.13,2109.13 579.13,1950.87 613.94,1916.06 711.06,1916.06 739.52,1944.52 818.66,1944.52 838.66,1924.52 1020.82,1924.52 1035.82,1909.52 1262.48,1909.52 1311.5,1860.5 1449,1860.5 1465.49,1844.01 1465.49,1187.2 1542.14,1110.54 1687.77,1110.54 v1(1893.92,1316.68)
AM263_PORZ_RC: C63.1 R19.2 U6.2 | length 113.5
  Top Layer w5.3: U6.2@2152.96,752.39 2182.18,752.39 2190.8,743.77 C63.1@2207.84,743.77 R19.2@2262.84,743.77
AM263_PR0_MDIO0_MDC: R71.1 R73.1 U17.2 | length 445.2
  Top Layer w5.3: R71.1@4331.94,1071.65 v1(4360,1071.65)
  Bottom Layer w5.3: v1(4360,1071.65) 4384.34,1047.31 4384.34,1021.78 4439.41,966.71 4570,966.71 4588.41,985.13 R73.1@4588.41,1010.55 4623.28,1010.55 4636.79,1024.06 U17.2@4680.08,1024.06
AM263_PR0_MDIO0_MDC_R: R71.2 U1.L18 | length 211.2
  Top Layer w5.3: U1.L18@4082.57,1067.83 4100.96,1067.83 4103.77,1070.65 R71.2@4292.57,1070.65
AM263_PR0_MDIO0_MDIO: R72.1 R74.1 U17.4 | length 250.1
  Top Layer w5.3: R72.1@4471.3,1086.73 4570.89,1086.73 v1(4588.41,1104.25)
  Bottom Layer w5.3: v1(4588.41,1104.25) R74.1@4588.41,1074.9 4619.79,1074.9 4631.26,1063.43 U17.4@4680.08,1063.43
AM263_PR0_MDIO0_MDIO_R: R72.2 U1.L17 | length 403.6
  Top Layer w4: U1.L17@4051.07,1067.83 4059.88,1059.02
  Top Layer w5.3: 4059.88,1059.02 4067.72,1051.18 4396.38,1051.18 4422.77,1077.57 4422.77,1079.54 4429.96,1086.73 R72.2@4431.93,1086.73
AM263_PRU_MUX_SEL_GPIO64: R287.2 R289.2 U1.J3 U23.9 U23.10 U49.1 | length 3547.3
  Top Layer w5.3: v1(4426.91,1191.61) 4456.29,1191.61 4511.32,1246.64 4511.32,1323.6 4528.38,1340.65 4620.51,1340.65 4640.24,1360.38 4640.24,1397.6 4689.41,1446.77 4704.17,1446.77 ; U23.10@4762.24,1436.81 4714.13,1436.81 4704.17,1446.77 ; U23.9@4762.24,1456.5 4713.9,1456.5 4704.17,1446.77 ; R289.2@5465.31,934.34 5466.14,935.17 R287.2@5530,935.17 5530.85,934.32 5591.07,934.32 5610.59,914.8 U49.1@5652.8,914.8 ; R289.2@5465.31,935.17 5445,935.17 5435,925.17 5435,853.97 5485.91,803.06 5541.94,803.06 5610,735 v1(5610,665.82)
  Top Layer w10: v1(3594.38,1146.57) U1.J3@3610.12,1130.83
  SIG 1 w4.75: v1(3594.38,1146.57) 3629.34,1111.61 4119.55,1111.61 4187.36,1179.42 4271.85,1179.42 4300.52,1150.75 4413.26,1150.75 4426.91,1164.4 v1(4426.91,1191.61) 4440,1191.61 4452.46,1179.15 4452.46,1119.78 4624.65,947.59 4835.18,947.59 5003.52,779.25 5050.22,779.25 5106.32,723.15 5257.38,723.15 5314.12,666.41 5609.42,666.41 v1(5610,665.82)
AM263_QSPI0_CLK: R26.1 U7.6 | length 101.9
  Top Layer w5.3: R26.1@2810,848.65 2810,872.95 2826.45,889.39 2838.55,889.39 2850,900.85 U7.6@2850,926.92
AM263_QSPI0_CLK_R: R26.2 U1.N2 | length 1425.2
  Top Layer w5.3: v1(2810,782.15) R26.2@2810,809.28
  Top Layer w10: v1(3562.88,989.09) U1.N2@3578.63,1004.84
  SIG 1 w4: 3515.64,961.01 3543.72,989.09 v1(3562.88,989.09)
  SIG 1 w4.75: v1(2810,782.15) 2787.15,805 2724.16,805 2705.75,823.41 2705.75,909.44 2714.16,917.85 2756.25,917.85 2765,909.1 2765,848.87 2812.47,801.4 2870.43,801.4 2880.75,811.72 2880.75,879.87 2889.41,888.53 2961.1,888.53 2990.49,859.13 3128.8,859.13 3135,865.33 3135,889.12 3143.08,897.2 3167.67,897.2 3175.75,889.12 3175.75,877.15 3183.28,869.63 3204.5,869.63 3222.03,887.15 3242.03,887.15 3288.53,840.65 3385.65,840.65 3482.34,937.34 3491.97,937.34 3515.64,961.01
AM263_QSPI0_CSN0: R31.1 U1.P1 U7.1 | length 1516.4
  Top Layer w5.3: v1(2950,1197.52) U7.1@2950,1232.08 ; v1(3314.74,880) 3301.21,893.53 R31.1@3278.62,893.53 3278.62,934.58 3322.87,978.83 3541.65,978.83 U1.P1@3547.13,973.35
  SIG 1 w4.75: v1(2950,1197.52) 2896.93,1197.52 2889.41,1190 2889.41,1164.98 2897.73,1156.66 2932.3,1156.66 2950,1138.96 2950,1023.97 2936.29,1010.25 2920,1010.25 2913.78,1004.03 2913.78,990.81 2920,984.59 3044.66,984.59 3055.48,973.77 3055.48,962.51 3067.03,950.96 3089.1,950.96 3148.41,1010.27 3224.33,1010.27 3244.85,989.75 3244.85,948.06 3253.55,939.36 3274.13,939.36 3280,945.22 3280,1001.96 3287.65,1009.61 3315.1,1009.61 3322.05,1002.66 3322.05,971.47 3330.82,962.69 3362.31,962.69 3370,955 3370,934.4 3361.44,925.84 3330,925.84 3314.74,910.58 v1(3314.74,880)
AM263_QSPI0_D0: R27.2 R42.1 U1.N1 | length 1419.4
  Top Layer w5.3: v1(2760,782.15) R27.2@2760,809.28 ; v1(3115,885.51) 3137.48,907.99 3137.48,930.94 3144.95,938.42 R42.1@3164.53,938.42 3183.79,938.42 3199.89,922.33 3250.39,922.33 3317.49,989.43 3531.72,989.43 U1.N1@3547.13,1004.84
  SIG 1 w4.75: v1(2760,782.15) 2751.25,790.91 2719.85,790.91 2691.67,819.08 2691.67,909.57 2710,927.9 2775.6,927.9 2781.75,921.75 2781.75,873.25 2789.1,865.9 2803.21,865.9 2809.94,872.64 2809.94,922.84 2815,927.9 2835,927.9 2840,922.9 2840,878.53 2848.53,870 2861.18,870 2870,878.82 2870,917.9 2880,927.9 2900,927.9 2906.67,921.22 2906.67,909.03 2913.78,901.93 2933.86,901.93 2940,908.07 2940,920 2947.9,927.9 2989.08,927.9 3003.05,913.93 3003.05,903.37 3037.24,869.18 3098.67,869.18 v1(3115,885.51)
AM263_QSPI0_D1: R28.2 R43.1 U1.N4 | length 1431.9
  Top Layer w5.3: v1(2753.36,1241.06) 2753.36,1299.79 2792.84,1339.27 R28.2@2810.31,1339.27
  Top Layer w10: v1(3625.87,989.09) U1.N4@3641.62,1004.84
  SIG 1 w4: 3515.64,1005 3609.97,1005 v1(3625.87,989.09)
  SIG 1 w4.75: v1(2753.36,1241.06) 2753.36,1214.1 2744.76,1205.49 2744.76,1056.06 2842.36,958.46 3000.42,958.46 3052.03,906.85 3094.91,906.85 3109.16,921.11 3236.68,921.11 3297.03,860.75 3325.62,860.75 3427.56,962.69 3427.56,971.06 3461.5,1005 3515.64,1005
  Bottom Layer w5.3: v1(2753.36,1241.06) R43.1@2753.36,1285
AM263_QSPI0_D2: R29.2 U1.M4 | length 1456.5
  Top Layer w5.3: v1(2764.01,1197.52) 2777.83,1211.34 2777.83,1279.01 2792.36,1293.54 R29.2@2810.31,1293.54
  Top Layer w10: v1(3625.87,1020.59) U1.M4@3641.62,1036.34
  SIG 1 w4.75: v1(2764.01,1197.52) 2764.01,1091.25 2770.26,1085 2795,1085 2800,1090 2800,1161.66 2813.34,1175 2826.41,1175 2836.25,1165.16 2836.25,1155.32 2845,1146.57 2861.18,1146.57 2868.96,1154.35 2868.96,1211.64 2874.08,1216.77 2958.62,1216.77 2976.86,1198.53 2976.86,1095.07 3035.96,1035.97 3232.29,1035.97 3276.33,1080 3536.7,1080 3579.99,1036.71 3609.75,1036.71 v1(3625.87,1020.59)
AM263_QSPI0_D3: R30.2 U1.P3 | length 1409.9
  Top Layer w5.3: v1(2860,782.15) 2841.39,782.15 2835,788.55 2835,802.33 2841.95,809.28 R30.2@2860,809.28
  Top Layer w10: v1(3594.38,957.6) U1.P3@3610.12,973.35
  SIG 1 w4.75: v1(2860,782.15) 2909.64,782.15 2927.49,800 2927.49,865 2936.27,873.79 2946.21,873.79 2953.14,866.86 2953.14,813.72 2960,806.86 2976.86,806.86 2983.86,813.86 2983.86,841.28 2990.46,847.89 3008.45,847.89 3014.84,841.5 3014.84,824.79 3020.76,818.87 3039.43,818.87 3045.56,825 3045.56,844.8 3049.83,849.08 3075.17,849.08 3079.84,844.41 3079.84,813.72 3086.7,806.86 3103.55,806.86 3110.56,813.86 3110.56,840.42 3117.14,847 3138.92,847 3144.84,841.09 3144.84,813.72 3151.7,806.86 3168.55,806.86 3175.56,813.86 3175.56,844.8 3180,849.25 3217.95,849.25 3223.9,843.3 3223.9,832.57 3235.56,820.9 3431.69,820.9 3435.73,824.95 3435.73,833.39 3420,849.12 3420,855.65 3427.21,862.86 3435.3,862.86 3450.28,847.89 3461.08,847.89 3470,856.8 3470,862.64 3455,877.64 3455,890.65 3466.27,901.93 3474.05,901.93 3481.37,894.6 3505.39,894.6 3531.39,920.6 3531.39,928.98 3518.13,942.23 3518.13,950.93 3535.99,968.79 3545,968.79 3549.75,964.04 3549.75,955.08 3557.7,947.13 3583.91,947.13 v1(3594.38,957.6)
AM263_RESETN_PB: R5.1 R179.1 U33.4 | length 1887.4
  Top Layer w5.3: v1(769.09,2182.15) 735.61,2148.67 735.61,2065.27 747.14,2053.74 R179.1@769.09,2053.74 U33.4@819.08,2053.74
  Bottom Layer w5.3: v1(769.09,2182.15) 791.24,2160 1130,2160 1140,2170 1323.21,2170 1392.71,2100.5 1499.5,2100.5 1555.5,2044.5 1555.5,1934.5 1589.93,1900.07 1609.93,1900.07 1677.36,1832.64 1854.61,1832.64 1886.96,1865 2000,1865 2048.11,1816.89 R5.1@2048.11,1678.29
AM263_RGMII1_RD0: U1.U17 U50.41 | length 1437.5
  Top Layer w5.3: U1.U17@4051.07,878.86 4066.92,863.01 4066.92,807.86 4119.04,755.74 4345.31,755.74 v1(4418.22,828.66) ; v1(5042.25,760) 5064.19,738.05 5214.98,738.05 5228.38,751.46 5228.38,773.99 5248.23,793.84 U50.41@5248.23,846.81
  Bottom Layer w5.3: v1(4418.22,828.66) 4678.37,828.66 4747.02,760 v1(5042.25,760)
AM263_RGMII1_RD1: U1.T17 U50.39 | length 1437.8
  Top Layer w4: U1.T17@4051.07,910.35 4068.04,893.38 4088.58,893.38
  Top Layer w5.3: 4088.58,893.38 4097.09,884.87 4097.09,870.6 4181.82,785.87 v1(4325,785.87) ; v1(5042.25,806.62) 5200.48,806.62 5208.86,815 U50.39@5208.86,846.81
  Bottom Layer w5.3: v1(4325,785.87) 4396.74,857.6 4674.33,857.6 4685.56,846.38 5007.17,846.38 5041.65,880.85 5071.86,880.85 5080,872.72 5080,821.62 5065,806.62 v1(5042.25,806.62)
AM263_RGMII1_RD2: U1.U18 U50.38 | length 1591.7
  Top Layer w5.3: U1.U18@4082.57,878.86 4082.57,870.13 4098.22,854.48 4098.22,791.55 4108.91,780.87 4122.22,780.87 4127.72,786.36 4127.72,800 4135.42,807.7 4145,807.7 4160,792.7 4160,775 4168.66,766.34 4340.92,766.34 4398.69,824.12 4398.69,836.74 4494,932.05 4851.59,932.05 4878.64,905 4878.64,805.54 4891.48,792.7 4939.35,792.7 4954.45,807.8 4977.2,807.8 4995.37,789.63 5010.1,789.63 5019.79,799.32 5019.79,843.75 5027.3,851.27 5043.73,851.27 5050,845 5050,826.48 5059.26,817.22 5070.4,817.22 5076.16,822.99 5076.16,845 5082.43,851.27 5096.48,851.27 5102.75,845 5102.75,824.02 5109.55,817.22 5128.99,817.22 5135,823.23 5135,852.56 5145,862.56 U50.38@5173.43,862.56
AM263_RGMII1_RD3: U1.T18 U50.36 | length 1592.6
  Top Layer w5.3: U1.T18@4082.57,910.35 4089.95,910.35 4108.48,891.83 4108.48,876.22 4185.38,799.32 4201.77,799.32 4210,807.55 4210,825.34 4216.67,832.01 4229.42,832.01 4236.08,825.35 4236.08,814.32 4245,805.39 4351.47,805.39 4488.73,942.65 4860,942.65 4890,912.65 4890,809.17 4895.88,803.3 4916.09,803.3 4923.6,810.8 4923.6,895.52 4930,901.93 4950,901.93 4955,896.93 4955,825 4960,820 4984.47,820 4990,825.53 4990,855 4999.32,864.32 5098.42,864.32 5098.46,864.28 5103.12,864.28 5112.25,873.41 5112.25,894.17 5120,901.93 U50.36@5173.43,901.93
AM263_RGMII1_RX_CTL: U1.R18 U50.34 | length 1592.3
  Top Layer w4: U1.R18@4082.57,941.85 4086.6,941.85 4093.63,934.82
  Top Layer w5.3: 4093.63,934.82 4118.93,909.52 4161.79,909.52 4168.18,903.13 4168.18,876.09 4177.75,866.53 4211.18,866.53 4258.64,819.06 4349.1,819.06 4483.29,953.25 4890.02,953.25 4900.6,942.67 4900.6,916.3 4906.9,910 4916.73,910 4923.6,916.86 4923.6,948.6 4928.27,953.27 4943.52,953.27 4948.18,948.61 4948.18,918.55 4954.21,912.53 4965.46,912.53 4970.21,917.28 4970.21,939.73 4974.59,944.11 4983.35,944.11 5000.27,927.2 5000.27,882.83 5008.18,874.92 5024.92,874.92 5032.8,882.8 5032.8,945.01 5041.88,954.08 5055.45,954.08 5068.18,941.36 5068.18,881.61 5073.45,876.34 5093.6,876.34 5097,879.73 5097,931.84 5106.46,941.3 U50.34@5173.43,941.3
AM263_RGMII1_RXC: U1.R17 U50.32 | length 1440.6
  Top Layer w4: U1.R17@4051.07,941.85 4065.27,927.65 4083.18,927.65
  Top Layer w5.3: 4082.85,927.33 4086.13,927.33 4117.78,895.68 4117.78,881.91 4152.69,847 v1(4200.6,847) ; v1(5076.16,960.98) 5098.77,960.98 5118.46,980.67 U50.32@5173.43,980.67
  Bottom Layer w5.3: v1(4200.6,847) 4238.27,809.34 4297.21,809.34 4312.89,825.02 4312.89,959.86 4323.88,970.85 4354.64,970.85 4365,960.5 4365,921.1 4378.24,907.86 4772.26,907.86 4808.32,871.8 4986.98,871.8 v1(5076.16,960.98)
AM263_RGMII1_TD0: R65.1 U50.29 | length 1175.3
  Top Layer w5.3: R65.1@4331.94,840.82 4349.88,840.82 4473.84,964.78 4521.39,964.78 4528.28,971.67 4528.28,987.74 4532.77,992.22 4546.12,992.22 4552.9,985.45 4552.9,968.99 4557.11,964.78 4568.94,964.78 4575.18,971.02 4575.18,984.91 4579.44,989.16 4600.29,989.16 4604.81,984.65 4604.81,969.97 4610,964.78 4624.12,964.78 4630,970.65 4630,1007.09 4634.98,1012.07 4647.7,1012.07 4654.4,1005.36 4654.4,970.1 4659.72,964.78 4948.5,964.78 4957.98,974.26 4957.98,1032.47 4964,1038.49 4975,1038.49 4980,1033.49 4980,1022.95 4985,1017.95 4993.22,1017.95 5000.27,1025 5000.27,1033.76 5005,1038.49 5057.49,1038.49 5064.19,1031.78 5064.19,1019.4 5071.52,1012.07 5090.8,1012.07 5118.46,1039.72 U50.29@5173.43,1039.72
AM263_RGMII1_TD0_R: R65.2 U1.P16 | length 471.4
  Top Layer w5.3: v1(4264.5,840.82) R65.2@4292.57,840.82
  Top Layer w10: U1.P16@4019.57,973.35 v1(4035.32,957.6)
  SIG 1 w4.75: v1(4035.32,957.6) 4059.2,933.72 4185.46,933.72 4196.74,922.44 4196.74,898.46 4205.21,890 4220.39,890 4227.97,897.58 4227.97,926.69 4235,933.72 4272.73,933.72 4284.95,921.51 4284.95,861.26 v1(4264.5,840.82)
AM263_RGMII1_TD1: R66.1 U50.27 | length 1376.8
  Top Layer w5.3: R66.1@4331.94,878.82 4340.76,870 4364.07,870 4377.59,883.52 4377.59,905.86 4385,913.27 4407.24,913.27 4415,921.02 4415,943.27 4425,953.27 4447.34,953.27 4469.45,975.38 4500,975.38 4528.28,1003.66 4528.28,1030.56 4539.56,1041.84 4550,1041.84 4555,1036.84 4555,1009.76 4565,999.76 4578.18,999.76 4588.41,1010 4588.41,1031.67 4626.25,1069.5 4641.65,1069.5 4646.89,1064.26 4646.89,1032.6 4665,1014.49 4665,981.36 4670.98,975.38 4684.53,975.38 4687.63,978.48 4687.63,1022.71 4693.35,1028.43 4704.79,1028.43 4711.41,1021.81 4711.41,980.71 4716.74,975.38 4726.97,975.38 4731.5,979.91 4731.5,1001.04 4736.72,1006.26 4750,1006.26 4755.96,1000.29 4755.96,980.94 4761.52,975.38 4771.27,975.38 4776.02,980.14 4776.02,1002.28 4780,1006.26 4799.14,1006.26 4804.17,1001.23 4804.17,984.39 4813.19,975.38 4937.77,975.38 4947.38,984.99 4947.38,1039.9 4956.57,1049.09 5068.18,1049.09 5078.65,1059.57 5102.75,1059.57 5122.28,1079.09 U50.27@5173.43,1079.09
AM263_RGMII1_TD1_R: R66.2 U1.P17 | length 288.2
  Top Layer w4: U1.P17@4051.07,973.35 4068.69,955.72 4085,955.72
  Top Layer w5.3: 4085,956.37 4088.58,956.37 4124.83,920.12 4175,920.12 4225.12,870 4283.75,870 R66.2@4292.57,878.82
